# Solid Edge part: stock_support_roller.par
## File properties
Title: Stock support roller
Author: Abhinav Rai
Template: Normal.par
Last saved by: SOFT
Revision: 18
Application: Solid Edge
Accuracy: 0.99
Material: aluminum
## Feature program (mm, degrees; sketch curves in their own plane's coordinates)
sketch for "unnamed RevolvedProtrusion 1" plane through (0, 0, 0) normal (0, -1, 0) x-axis (1, 0, 0)
  line (60, 0) -> (60, 18.669)
  line (60, 18.669) -> (15.55, 18.669)
  line (15.55, 18.669) -> (15.55, 92.075)
  line (15.55, 92.075) -> (-2.2388, 92.075)
  line (-2.2388, 92.075) -> (-111.45, 29.0219)
  line (-220.6612, 92.075) -> (-111.45, 29.0219)
  line (-238.45, 92.075) -> (-220.6612, 92.075)
  line (-238.45, 18.669) -> (-238.45, 92.075)
  line (-282.9, 18.669) -> (-238.45, 18.669)
  line (-282.9, 0) -> (-282.9, 18.669)
revolve "unnamed RevolvedProtrusion 1" add full turn 360 deg about sketch line (-282.9, 0) -> (60, 0)
chamfer "unnamed Chamfer 1"
fillet "Round_1" radius 1.5748
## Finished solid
Body 1: solid body, 14 faces, 13 edges, 0 vertices.
  Faces by surface: cone 4, cylinder 4, plane 4, torus 2
  Edges by curve: circle 13
Bounding box of the edges (mm; curved faces can reach further): 342.900 x 184.150 x 184.150, from (-282.9, -92.075, -92.075) to (60, 92.075, 92.075).
Cylindrical faces by radius (mm): R18.669 x2, R92.075 x2
Conical faces (half-angle, radius in mm at the cone's reference point): 30 deg R29.0219 x1, 30 deg R92.075 x1, 45 deg R17.0942 x1, 45 deg R18.669 x1
Toroidal faces (ring radius, tube radius in mm): R20.2438 r1.5748 x2
Planar faces by outward normal: +x 2, -x 2
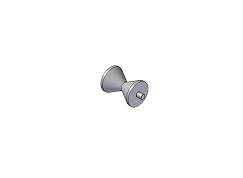
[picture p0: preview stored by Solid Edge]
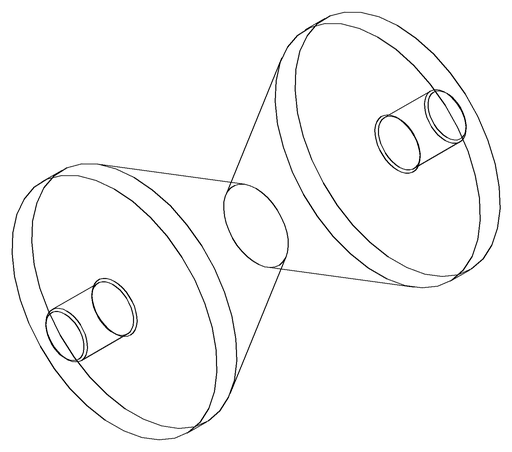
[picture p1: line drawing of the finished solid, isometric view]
